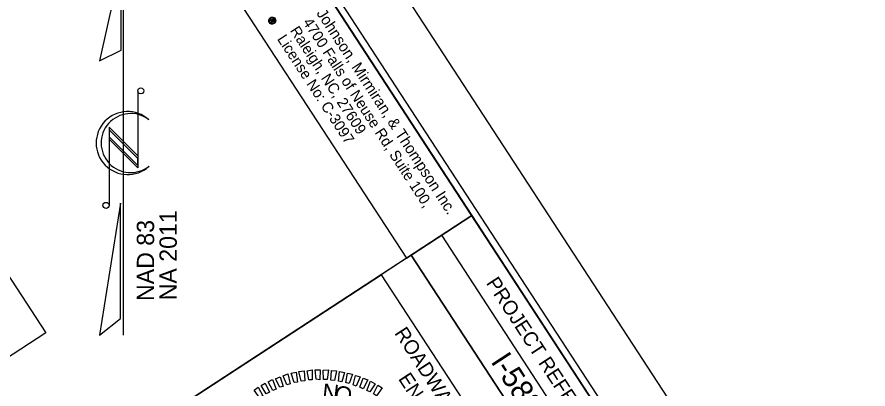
# Model space of a CAD drawing. Extents: x 1639622 to 2864602, y 842655 to 973236.
# Drawn here: x 1641163.7 to 1641458.9, y 843362.5 to 843491.5 of the extents above; entities that cross this region are included whole.
import ezdxf

# ---------------------------------------------------------------- set-up
doc = ezdxf.new("R2010")
doc.units = 0
for name, color, linetype in [('Old_Level_2', 7, 'Continuous'), ('Prop Dimension Text', 7, 'Continuous'), ('Prop Horizontal Alignment Curve and Spiral Data', 7, 'Continuous'), ('Sheet Data Field CELL', 7, 'Continuous'), ('Sheet North Arrow CELL', 7, 'Continuous'), ('Sheet Plan CELL', 7, 'Continuous'), ('Sheet Plot Border Inside CELL', 7, 'Continuous'), ('Sheet Plot Border Outside CELL', 7, 'Continuous')]:
    doc.layers.add(name, color=color, linetype=linetype)

msp = doc.modelspace()

# ---------------------------------------------------------------- linework, layer by layer
at = {"layer": 'Old_Level_2'}
for points in [[(1641259.78, 843364.78), (1641258.74, 843367.99), (1641260.46, 843368.34), (1641261.01, 843364.92)], [(1641262.27, 843365.21), (1641261.44, 843368.56), (1641263.23, 843368.82), (1641263.51, 843365.42)], [(1641264.84, 843365.69), (1641264.26, 843368.89), (1641266.04, 843369.15), (1641266.02, 843365.73)], [(1641267.41, 843365.91), (1641267.07, 843369.22), (1641268.86, 843369.17), (1641268.66, 843365.75)], [(1641270.02, 843365.79), (1641269.91, 843369.12), (1641271.72, 843369.15), (1641271.23, 843365.78)], [(1641272.55, 843365.6), (1641272.71, 843369), (1641274.48, 843368.81), (1641273.74, 843365.52)], [(1641275.22, 843365.2), (1641275.5, 843368.61), (1641277.23, 843368.21), (1641276.38, 843364.98)], [(1641252.36, 843362.03), (1641250.74, 843364.97), (1641252.33, 843365.8), (1641253.54, 843362.51)], [(1641254.8, 843363.18), (1641253.33, 843366.09), (1641255, 843366.79), (1641255.94, 843363.45)], [(1641257.26, 843364.02), (1641256, 843367.09), (1641257.64, 843367.75), (1641258.4, 843364.29)], [(1641277.7, 843364.8), (1641278.31, 843368), (1641280.06, 843367.66), (1641278.86, 843364.39)], [(1641280.22, 843363.98), (1641281.03, 843367.25), (1641282.73, 843366.7), (1641281.34, 843363.54)], [(1641282.63, 843363.21), (1641283.75, 843366.31), (1641285.34, 843365.74), (1641283.79, 843362.61)], [(1641247.94, 843359.41), (1641245.9, 843362.14), (1641247.37, 843363.13), (1641248.98, 843360.12)], [(1641250.13, 843360.84), (1641248.31, 843363.71), (1641249.8, 843364.59), (1641251.23, 843361.45)], [(1641285, 843362.04), (1641286.25, 843365.23), (1641287.86, 843364.36), (1641286.08, 843361.57)], [(1641287.3, 843360.89), (1641288.79, 843363.91), (1641290.3, 843362.98), (1641288.34, 843360.2)]]:
    msp.add_lwpolyline(points, close=True, dxfattribs=at)
at = {"layer": 'Prop Dimension Text'}
for p, q in [((1641251.42, 843489.75), (1641251.22, 843489.62)), ((1641251.22, 843489.62), (1641251.42, 843489.75)), ((1641251.23, 843489.62), (1641251.22, 843489.62)), ((1641251.42, 843489.75), (1641251.43, 843489.75)), ((1641251.53, 843490.35), (1641252.43, 843490.94)), ((1641251.66, 843490.15), (1641251.53, 843490.35)), ((1641252.02, 843490.38), (1641251.66, 843490.15)), ((1641252.12, 843490.21), (1641252.02, 843490.38)), ((1641252.29, 843490.32), (1641252.12, 843490.21)), ((1641252.12, 843490.21), (1641252.29, 843490.32)), ((1641252.13, 843490.2), (1641252.12, 843490.21)), ((1641252.39, 843490.62), (1641252.18, 843490.48)), ((1641252.18, 843490.48), (1641252.29, 843490.32)), ((1641252.29, 843490.32), (1641252.29, 843490.31)), ((1641252.5, 843490.46), (1641252.39, 843490.62)), ((1641252.43, 843490.94), (1641252.67, 843490.57)), ((1641252.67, 843490.57), (1641252.5, 843490.46)), ((1641252.5, 843490.46), (1641252.67, 843490.57)), ((1641252.51, 843490.43), (1641252.5, 843490.46)), ((1641252.67, 843490.57), (1641252.71, 843490.51)), ((1641253.2, 843490.92), (1641253.01, 843490.79)), ((1641253.01, 843490.79), (1641253.2, 843490.92))]:
    msp.add_line(p, q, dxfattribs=at)
msp.add_lwpolyline([(1641216.75, 843533.53), (1641298.74, 843407.89), (1641321.42, 843422.68), (1641239.43, 843548.33)], close=True, dxfattribs=at)
msp.add_lwpolyline([(1641252.24, 843489.73), (1641252.19, 843489.7), (1641252.16, 843489.67), (1641252.13, 843489.65), (1641252.05, 843489.56), (1641251.93, 843489.75)], dxfattribs=at)
for points, degree in [([(1641251.22, 843489.62), (1641251.05, 843489.89), (1641250.99, 843490.2), (1641251.06, 843490.52), (1641251.12, 843490.84), (1641251.29, 843491.09), (1641251.57, 843491.27), (1641251.85, 843491.45), (1641252.15, 843491.51), (1641252.46, 843491.43), (1641252.77, 843491.36), (1641253.02, 843491.19), (1641253.2, 843490.92)], 3), ([(1641252.88, 843489.27), (1641252.6, 843489.09), (1641252.3, 843489.03), (1641251.98, 843489.09), (1641251.66, 843489.17), (1641251.41, 843489.34), (1641251.23, 843489.62)], 3), ([(1641253.01, 843490.79), (1641252.87, 843491.01), (1641252.67, 843491.15), (1641252.42, 843491.21), (1641252.17, 843491.27), (1641251.92, 843491.22), (1641251.7, 843491.08), (1641251.48, 843490.93), (1641251.33, 843490.72), (1641251.28, 843490.47), (1641251.23, 843490.21), (1641251.28, 843489.97), (1641251.42, 843489.75)], 3), ([(1641251.43, 843489.75), (1641251.57, 843489.52), (1641251.77, 843489.38), (1641252.02, 843489.33), (1641252.28, 843489.28), (1641252.53, 843489.32), (1641252.75, 843489.47), (1641252.97, 843489.61), (1641253.11, 843489.82), (1641253.17, 843490.08), (1641253.21, 843490.33), (1641253.16, 843490.57), (1641253.01, 843490.79)], 3), ([(1641251.93, 843489.75), (1641251.96, 843489.8), (1641252, 843489.85), (1641252.06, 843489.89), (1641252.14, 843489.95), (1641252.19, 843489.99), (1641252.2, 843490.03)], 3), ([(1641252.2, 843490.03), (1641252.2, 843490.06), (1641252.18, 843490.12), (1641252.13, 843490.2)], 2), ([(1641252.4, 843489.97), (1641252.4, 843489.89), (1641252.35, 843489.81), (1641252.24, 843489.73)], 2), ([(1641252.29, 843490.31), (1641252.38, 843490.18), (1641252.46, 843490.14), (1641252.53, 843490.19), (1641252.6, 843490.23), (1641252.59, 843490.31), (1641252.51, 843490.43)], 3), ([(1641252.71, 843490.51), (1641252.86, 843490.28), (1641252.84, 843490.11), (1641252.66, 843489.99), (1641252.58, 843489.94), (1641252.49, 843489.93), (1641252.4, 843489.97)], 3), ([(1641253.2, 843490.92), (1641253.38, 843490.64), (1641253.44, 843490.34), (1641253.38, 843490.02), (1641253.33, 843489.71), (1641253.15, 843489.45), (1641252.88, 843489.27)], 3)]:
    msp.add_open_spline(points, degree=degree, dxfattribs=at)
at = {"layer": 'Prop Horizontal Alignment Curve and Spiral Data'}
msp.add_lwpolyline([(1641046, 843577.64), (1641173.64, 843382.04), (1641010.85, 843275.81), (1640883.22, 843471.41)], close=True, dxfattribs=at)
at = {"layer": 'Sheet North Arrow CELL'}
for p, q in [((1641200.65, 843381.18), (1641200.65, 843511.18)), ((1641205.55, 843465.94), (1641205.55, 843439.26)), ((1641209.23, 843456), (1641209.37, 843455.9)), ((1641205.55, 843443.42), (1641195.61, 843453.36)), ((1641195.61, 843453.36), (1641195.61, 843426.24)), ((1641205.55, 843442.44), (1641195.61, 843452.38)), ((1641195.61, 843452.38), (1641195.61, 843449.94)), ((1641205.55, 843440), (1641195.61, 843449.94)), ((1641195.61, 843449.94), (1641205.55, 843440)), ((1641205.55, 843439.26), (1641195.61, 843449.2)), ((1641205.55, 843440), (1641205.55, 843442.44))]:
    msp.add_line(p, q, dxfattribs=at)
for points in [[(1641199.75, 843510.04), (1641192.33, 843476.28), (1641199.75, 843480.04)], [(1641199.59, 843426.98), (1641192.23, 843381.18), (1641199.59, 843386.98)]]:
    msp.add_lwpolyline(points, close=True, dxfattribs=at)
for centre in [(1641206.61, 843465.92), (1641194.55, 843426.2)]:
    msp.add_circle(centre, 1.06, dxfattribs=at)
for centre, radius, start, end in [((1641202.03, 843447.81), 10.92, 47.84, 312.3941), ((1641203.09, 843447.81), 10.24, 53.095, 308.6287)]:
    msp.add_arc(centre, radius, start, end, dxfattribs=at)
at = {"layer": 'Sheet Plan CELL'}
for p, q in [((1641310.9, 843415.83), (1641420.21, 843248.29)), ((1641300.41, 843408.97), (1641289.95, 843402.15)), ((1641300.41, 843408.97), (1641409.74, 843241.46)), ((1641300.41, 843408.97), (1641409.74, 843241.46))]:
    msp.add_line(p, q, dxfattribs=at)
for points in [[(1641430.74, 843255.12), (1640611, 844511.36), (1639731.66, 843937.55), (1640551.38, 842681.33)], [(1639731.66, 843937.55), (1640610.97, 844511.36), (1641321.42, 843422.68), (1641195.75, 843340.66), (1641305.06, 843173.13), (1640551.38, 842681.33)], [(1641321.42, 843422.68), (1641430.74, 843255.12), (1641409.74, 843241.46), (1641300.41, 843408.97)], [(1641289.95, 843402.15), (1641344.62, 843318.36), (1641250.4, 843256.87), (1641195.75, 843340.66)]]:
    msp.add_lwpolyline(points, close=True, dxfattribs=at)
at = {"layer": 'Sheet Plot Border Inside CELL'}
msp.add_lwpolyline([(1639645.67, 844064.72), (1640556.11, 842669.51), (1641439.64, 843246.03), (1640529.21, 844641.26)], close=True, dxfattribs=at)
at = {"layer": 'Sheet Plot Border Outside CELL'}
msp.add_lwpolyline([(1639621.82, 844064.68), (1640541.82, 842654.79), (1641458.85, 843253.19), (1640538.85, 844663.07)], close=True, dxfattribs=at)
msp.add_lwpolyline([(1639621.82, 844064.68), (1640541.82, 842654.79), (1641458.85, 843253.19), (1640538.85, 844663.07)], close=True, dxfattribs=at)

# ---------------------------------------------------------------- texts
at = {"layer": 'Old_Level_2'}
for s, rotation, p in [('N', 353.5494, (1641269.29, 843358.66)), ('O', 346.3476, (1641273.15, 843358.37))]:
    msp.add_text(s, height=5.9, rotation=rotation, dxfattribs=at).set_placement(p)
at = {"layer": 'Prop Dimension Text'}
for s, height, p in [('Johnson, Mirmiran, & Thompson Inc.', 3.8334, (1641267.39, 843492.79)), ('4700 Falls of Neuse Rd, Suite 100, ', 3.7239, (1641262.67, 843489.72)), ('Raleigh, NC, 27609', 3.7239, (1641258.22, 843486.81)), ('License No: C-3097', 3.7239, (1641253.76, 843483.9))]:
    msp.add_text(s, height=height, rotation=303.1259, dxfattribs=at).set_placement(p)
at = {"layer": 'Sheet Data Field CELL'}
msp.add_text('I-5880', height=7.5, rotation=303.1259, dxfattribs=at).set_placement((1641327.79, 843372.07))
at = {"layer": 'Sheet North Arrow CELL'}
for s, p in [('NA 2011', (1641219.09, 843393.29)), ('NAD 83', (1641211.22, 843393.05))]:
    msp.add_text(s, height=6, rotation=90, dxfattribs=at).set_placement(p)
at = {"layer": 'Sheet Plan CELL'}
for s, height, p in [('PROJECT REFERENCE NO.', 5.0001, (1641326.24, 843399.32)), ('ROADWAY DESIGN', 5.0001, (1641294.42, 843381.93)), ('ENGINEER', 5, (1641295.75, 843366.1))]:
    msp.add_text(s, height=height, rotation=303.1259, dxfattribs=at).set_placement(p)

doc.saveas('drawing.dxf')
